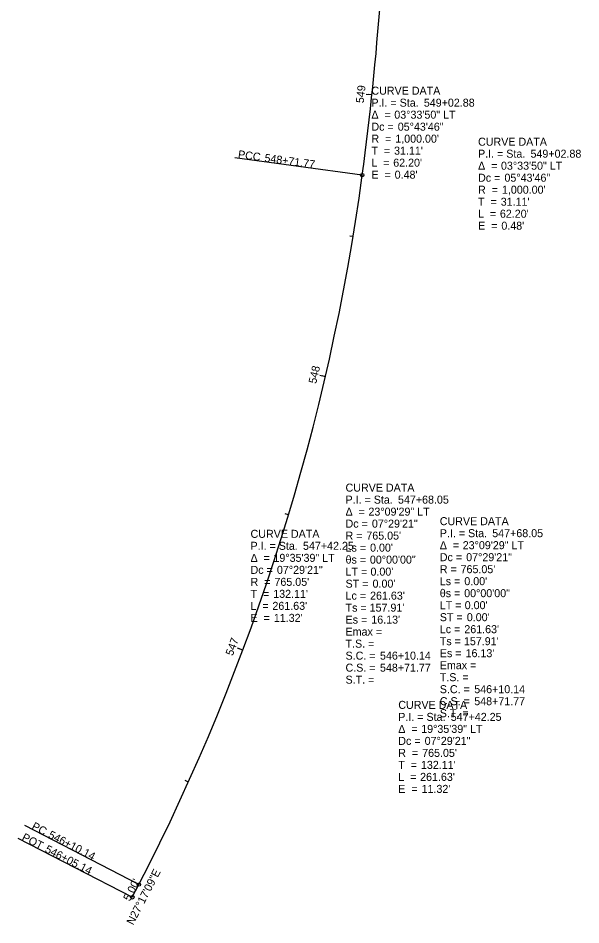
# Model space of a CAD drawing. Extents: x 1922787 to 1923078, y 359089 to 360354.
# Drawn here: x 1922800.9 to 1922998, y 359089.3 to 359406.6 of the extents above; entities that cross this region are included whole.
import ezdxf

# ---------------------------------------------------------------- set-up
doc = ezdxf.new("R2010")
doc.units = 0
for name, color, linetype in [('GE_P_Alignment', 7, 'Continuous'), ('GE_P_Alignment_1000_Curve_Data', 7, 'Continuous'), ('GE_P_Alignment_1000_Stations', 7, 'Continuous'), ('GE_P_Alignment_100_Curve_Data', 7, 'Continuous'), ('GE_P_Alignment_100_Stations', 7, 'Continuous'), ('GE_P_Alignment_500_Curve_Data', 7, 'Continuous'), ('GE_P_Alignment_500_Stations', 7, 'Continuous')]:
    doc.layers.add(name, color=color, linetype=linetype)

msp = doc.modelspace()

# ---------------------------------------------------------------- linework, layer by layer
at = {"layer": 'GE_P_Alignment'}
msp.add_line((1922840.87, 359098.92), (1922843.16, 359103.37), dxfattribs=at)
for centre, radius, start, end in [((1921930.4, 359485.54), 1000, 352.30833, 355.87222), ((1922163.24, 359454.09), 765.05, 332.71417, 352.30833)]:
    msp.add_arc(centre, radius, start, end, dxfattribs=at)
at = {"layer": 'GE_P_Alignment_1000_Stations'}
for p, q in [((1922921.4, 359351.69), (1922876.81, 359357.72)), ((1922843.16, 359103.37), (1922803.17, 359124)), ((1922840.87, 359098.92), (1922800.88, 359119.55))]:
    msp.add_line(p, q, dxfattribs=at)
for centre in [(1922921.4, 359351.69), (1922843.16, 359103.37), (1922840.87, 359098.92)]:
    msp.add_circle(centre, 0.6, dxfattribs=at)
at = {"layer": 'GE_P_Alignment_100_Stations'}
for p, q in [((1922924.79, 359379.72), (1922922.8, 359379.93)), ((1922921.4, 359351.69), (1922876.81, 359357.72)), ((1922918.18, 359330.16), (1922917, 359330.35)), ((1922908.48, 359281.12), (1922906.53, 359281.57)), ((1922895.59, 359232.82), (1922894.44, 359233.17)), ((1922879.58, 359185.46), (1922877.7, 359186.16)), ((1922860.5, 359139.25), (1922859.41, 359139.75)), ((1922843.16, 359103.37), (1922803.17, 359124)), ((1922840.87, 359098.92), (1922800.88, 359119.55))]:
    msp.add_line(p, q, dxfattribs=at)
for centre in [(1922921.4, 359351.69), (1922843.16, 359103.37), (1922840.87, 359098.92)]:
    msp.add_circle(centre, 0.6, dxfattribs=at)
at = {"layer": 'GE_P_Alignment_500_Stations'}
for p, q in [((1922924.79, 359379.72), (1922923.59, 359379.84)), ((1922921.4, 359351.69), (1922876.81, 359357.72)), ((1922908.48, 359281.12), (1922907.31, 359281.39)), ((1922879.58, 359185.46), (1922878.45, 359185.88)), ((1922843.16, 359103.37), (1922803.17, 359124)), ((1922840.87, 359098.92), (1922800.88, 359119.55))]:
    msp.add_line(p, q, dxfattribs=at)
for centre in [(1922921.4, 359351.69), (1922843.16, 359103.37), (1922840.87, 359098.92)]:
    msp.add_circle(centre, 0.6, dxfattribs=at)

# ---------------------------------------------------------------- texts
at = {"layer": 'GE_P_Alignment_1000_Curve_Data'}
for s, p in [('CURVE DATA', (1922924.61, 359379.82)), ('P.I. = Sta. ', (1922924.61, 359375.62)), ('549+02.88', (1922942.97, 359375.62)), ('Δ  = ', (1922924.61, 359371.42)), ('03°33\'50" LT', (1922932.63, 359371.42)), ('Dc = ', (1922924.61, 359367.22)), ('05°43\'46"', (1922933.84, 359367.22)), ('R  = ', (1922924.61, 359363.02)), ("1,000.00'", (1922932.97, 359363.02)), ('T  = ', (1922924.61, 359358.82)), ("31.11'", (1922932.54, 359358.82)), ('L  = ', (1922924.61, 359354.62)), ("62.20'", (1922932.25, 359354.62)), ('E  = ', (1922924.61, 359350.42)), ("0.48'", (1922932.76, 359350.42)), ('CURVE DATA', (1922915.55, 359240.9)), ('P.I. = Sta. ', (1922915.55, 359236.7)), ('547+68.05', (1922933.92, 359236.7)), ('Δ  = ', (1922915.55, 359232.5)), ('23°09\'29" LT', (1922923.57, 359232.5)), ('Dc = ', (1922915.55, 359228.3)), ('07°29\'21"', (1922924.79, 359228.3)), ('CURVE DATA', (1922882.28, 359224.73)), ('R = ', (1922915.55, 359224.1)), ("765.05'", (1922922.83, 359224.1)), ('P.I. = Sta. ', (1922882.28, 359220.53)), ('547+42.25', (1922900.65, 359220.53)), ('Ls = ', (1922915.55, 359219.9)), ("0.00'", (1922924.14, 359219.9)), ('Δ  = ', (1922882.28, 359216.33)), ('19°35\'39" LT', (1922890.3, 359216.33)), ('θs = ', (1922915.55, 359215.7)), ('00°00\'00"', (1922924.08, 359215.7)), ('Dc = ', (1922882.28, 359212.13)), ('07°29\'21"', (1922891.52, 359212.13)), ('LT = ', (1922915.55, 359211.5)), ("0.00'", (1922924.28, 359211.5)), ('R  = ', (1922882.28, 359207.93)), ("765.05'", (1922890.65, 359207.93)), ('ST = ', (1922915.55, 359207.3)), ("0.00'", (1922925.01, 359207.3)), ('T  = ', (1922882.28, 359203.73)), ("132.11'", (1922890.22, 359203.73)), ('Lc = ', (1922915.55, 359203.1)), ("261.63'", (1922924.14, 359203.1)), ('L  = ', (1922882.28, 359199.53)), ("261.63'", (1922889.93, 359199.53)), ('Ts = ', (1922915.55, 359198.9)), ("157.91'", (1922923.99, 359198.9)), ('E  = ', (1922882.28, 359195.33)), ("11.32'", (1922890.44, 359195.33)), ('Es = ', (1922915.55, 359194.7)), ("16.13'", (1922924.57, 359194.7)), ('Emax = ', (1922915.55, 359190.5)), ('T.S. = ', (1922915.55, 359186.3)), ('S.C. = ', (1922915.55, 359182.1)), ('546+10.14', (1922927.61, 359182.1)), ('C.S. = ', (1922915.55, 359177.9)), ('548+71.77', (1922927.61, 359177.9)), ('S.T. = ', (1922915.55, 359173.7))]:
    msp.add_text(s, height=2.8, dxfattribs=at).set_placement(p)
for s, p in [('N27°17\'09"E', (1922841.16, 359089.01)), ("5.00'", (1922840, 359097.34))]:
    msp.add_text(s, height=2.8, rotation=62.7142, dxfattribs=at).set_placement(p)
at = {"layer": 'GE_P_Alignment_1000_Stations'}
for s, rotation, p in [('PCC', 352.3083, (1922877.76, 359357.64)), ('548+71.77', 352.3083, (1922887.02, 359356.38)), ('PC', 332.7142, (1922805.38, 359122.91)), ('546+10.14', 332.7142, (1922811.18, 359119.92)), ('POT', 332.7142, (1922801.93, 359119.06)), ('546+05.14', 332.7142, (1922810.04, 359114.88))]:
    msp.add_text(s, height=2.8, rotation=rotation, dxfattribs=at).set_placement(p)
at = {"layer": 'GE_P_Alignment_100_Curve_Data'}
for s, p in [('CURVE DATA', (1922961.96, 359361.96)), ('P.I. = Sta. ', (1922961.96, 359357.76)), ('549+02.88', (1922980.33, 359357.76)), ('Δ  = ', (1922961.96, 359353.56)), ('03°33\'50" LT', (1922969.99, 359353.56)), ('Dc = ', (1922961.96, 359349.36)), ('05°43\'46"', (1922971.2, 359349.36)), ('R  = ', (1922961.96, 359345.16)), ("1,000.00'", (1922970.33, 359345.16)), ('T  = ', (1922961.96, 359340.96)), ("31.11'", (1922969.9, 359340.96)), ('L  = ', (1922961.96, 359336.76)), ("62.20'", (1922969.61, 359336.76)), ('E  = ', (1922961.96, 359332.56)), ("0.48'", (1922970.12, 359332.56)), ('CURVE DATA', (1922948.56, 359229.16)), ('P.I. = Sta. ', (1922948.56, 359224.96)), ('547+68.05', (1922966.93, 359224.96)), ('Δ  = ', (1922948.56, 359220.76)), ('23°09\'29" LT', (1922956.59, 359220.76)), ('Dc = ', (1922948.56, 359216.56)), ('07°29\'21"', (1922957.8, 359216.56)), ('R = ', (1922948.56, 359212.36)), ("765.05'", (1922955.84, 359212.36)), ('Ls = ', (1922948.56, 359208.16)), ("0.00'", (1922957.15, 359208.16)), ('θs = ', (1922948.56, 359203.96)), ('00°00\'00"', (1922957.1, 359203.96)), ('LT = ', (1922948.56, 359199.76)), ("0.00'", (1922957.29, 359199.76)), ('ST = ', (1922948.56, 359195.56)), ("0.00'", (1922958.02, 359195.56)), ('Lc = ', (1922948.56, 359191.36)), ("261.63'", (1922957.15, 359191.36)), ('Ts = ', (1922948.56, 359187.16)), ("157.91'", (1922957.01, 359187.16)), ('Es = ', (1922948.56, 359182.96)), ("16.13'", (1922957.59, 359182.96)), ('Emax = ', (1922948.56, 359178.76)), ('T.S. = ', (1922948.56, 359174.56)), ('S.C. = ', (1922948.56, 359170.36)), ('546+10.14', (1922960.63, 359170.36)), ('CURVE DATA', (1922934.02, 359164.87)), ('C.S. = ', (1922948.56, 359166.16)), ('548+71.77', (1922960.63, 359166.16)), ('P.I. = Sta. ', (1922934.02, 359160.67)), ('S.T. = ', (1922948.56, 359161.96)), ('547+42.25', (1922952.39, 359160.67)), ('Δ  = ', (1922934.02, 359156.47)), ('19°35\'39" LT', (1922942.05, 359156.47)), ('Dc = ', (1922934.02, 359152.27)), ('07°29\'21"', (1922943.26, 359152.27)), ('R  = ', (1922934.02, 359148.07)), ("765.05'", (1922942.39, 359148.07)), ('T  = ', (1922934.02, 359143.87)), ("132.11'", (1922941.96, 359143.87)), ('L  = ', (1922934.02, 359139.67)), ("261.63'", (1922941.67, 359139.67)), ('E  = ', (1922934.02, 359135.47)), ("11.32'", (1922942.18, 359135.47))]:
    msp.add_text(s, height=2.8, dxfattribs=at).set_placement(p)
for s, p in [('N27°17\'09"E', (1922841.16, 359089.01)), ("5.00'", (1922840, 359097.34))]:
    msp.add_text(s, height=2.8, rotation=62.7142, dxfattribs=at).set_placement(p)
at = {"layer": 'GE_P_Alignment_100_Stations'}
for s, rotation, p in [('549', 83.9256, (1922921.91, 359376.75)), ('PCC', 352.3083, (1922877.76, 359357.64)), ('548+71.77', 352.3083, (1922887.02, 359356.38)), ('548', 76.9331, (1922905.26, 359278.5)), ('547', 69.4439, (1922876.02, 359183.23)), ('PC', 332.7142, (1922805.38, 359122.91)), ('546+10.14', 332.7142, (1922811.18, 359119.92)), ('POT', 332.7142, (1922801.93, 359119.06)), ('546+05.14', 332.7142, (1922810.04, 359114.88))]:
    msp.add_text(s, height=2.8, rotation=rotation, dxfattribs=at).set_placement(p)
at = {"layer": 'GE_P_Alignment_500_Curve_Data'}
for s, p in [('CURVE DATA', (1922924.61, 359379.82)), ('P.I. = Sta. ', (1922924.61, 359375.62)), ('549+02.88', (1922942.97, 359375.62)), ('Δ  = ', (1922924.61, 359371.42)), ('03°33\'50" LT', (1922932.63, 359371.42)), ('Dc = ', (1922924.61, 359367.22)), ('05°43\'46"', (1922933.84, 359367.22)), ('R  = ', (1922924.61, 359363.02)), ("1,000.00'", (1922932.97, 359363.02)), ('T  = ', (1922924.61, 359358.82)), ("31.11'", (1922932.54, 359358.82)), ('L  = ', (1922924.61, 359354.62)), ("62.20'", (1922932.25, 359354.62)), ('E  = ', (1922924.61, 359350.42)), ("0.48'", (1922932.76, 359350.42)), ('CURVE DATA', (1922915.55, 359240.9)), ('P.I. = Sta. ', (1922915.55, 359236.7)), ('547+68.05', (1922933.92, 359236.7)), ('Δ  = ', (1922915.55, 359232.5)), ('23°09\'29" LT', (1922923.57, 359232.5)), ('Dc = ', (1922915.55, 359228.3)), ('07°29\'21"', (1922924.79, 359228.3)), ('CURVE DATA', (1922882.28, 359224.73)), ('R = ', (1922915.55, 359224.1)), ("765.05'", (1922922.83, 359224.1)), ('P.I. = Sta. ', (1922882.28, 359220.53)), ('547+42.25', (1922900.65, 359220.53)), ('Ls = ', (1922915.55, 359219.9)), ("0.00'", (1922924.14, 359219.9)), ('Δ  = ', (1922882.28, 359216.33)), ('19°35\'39" LT', (1922890.3, 359216.33)), ('θs = ', (1922915.55, 359215.7)), ('00°00\'00"', (1922924.08, 359215.7)), ('Dc = ', (1922882.28, 359212.13)), ('07°29\'21"', (1922891.52, 359212.13)), ('LT = ', (1922915.55, 359211.5)), ("0.00'", (1922924.28, 359211.5)), ('R  = ', (1922882.28, 359207.93)), ("765.05'", (1922890.65, 359207.93)), ('ST = ', (1922915.55, 359207.3)), ("0.00'", (1922925.01, 359207.3)), ('T  = ', (1922882.28, 359203.73)), ("132.11'", (1922890.22, 359203.73)), ('Lc = ', (1922915.55, 359203.1)), ("261.63'", (1922924.14, 359203.1)), ('L  = ', (1922882.28, 359199.53)), ("261.63'", (1922889.93, 359199.53)), ('Ts = ', (1922915.55, 359198.9)), ("157.91'", (1922923.99, 359198.9)), ('E  = ', (1922882.28, 359195.33)), ("11.32'", (1922890.44, 359195.33)), ('Es = ', (1922915.55, 359194.7)), ("16.13'", (1922924.57, 359194.7)), ('Emax = ', (1922915.55, 359190.5)), ('T.S. = ', (1922915.55, 359186.3)), ('S.C. = ', (1922915.55, 359182.1)), ('546+10.14', (1922927.61, 359182.1)), ('C.S. = ', (1922915.55, 359177.9)), ('548+71.77', (1922927.61, 359177.9)), ('S.T. = ', (1922915.55, 359173.7))]:
    msp.add_text(s, height=2.8, dxfattribs=at).set_placement(p)
for s, p in [('N27°17\'09"E', (1922841.16, 359089.01)), ("5.00'", (1922840, 359097.34))]:
    msp.add_text(s, height=2.8, rotation=62.7142, dxfattribs=at).set_placement(p)
at = {"layer": 'GE_P_Alignment_500_Stations'}
for s, rotation, p in [('PCC', 352.3083, (1922877.76, 359357.64)), ('548+71.77', 352.3083, (1922887.02, 359356.38)), ('PC', 332.7142, (1922805.38, 359122.91)), ('546+10.14', 332.7142, (1922811.18, 359119.92)), ('POT', 332.7142, (1922801.93, 359119.06)), ('546+05.14', 332.7142, (1922810.04, 359114.88))]:
    msp.add_text(s, height=2.8, rotation=rotation, dxfattribs=at).set_placement(p)

doc.saveas('drawing.dxf')
